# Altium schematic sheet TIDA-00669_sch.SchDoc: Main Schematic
size 431 x 279 mm; Date: Not shown in title block; ApprovedBy: Not shown in title block; CheckedBy: Not shown in title block; Author: Not shown in title block; CompanyName: Not shown in title block; DrawnBy: Gordon Varney; Engineer: Gordon Varney; Organization: Not shown in title block; Address1: Not shown in title block; Address2: Not shown in title block; Address3: Not shown in title block; Address4: Not shown in title block; DocumentNumber: 1; Revision: Use project parameter SCH_Rev; SheetNumber: 2; SheetTotal: 3; PageSetup: Record=PageOptions¦CenterHorizontal=True¦CenterVertical=True¦PrintScale=0.64¦XCorrection=1.00¦YCorrection=1.00¦PrintKind=0¦BorderSize=5000000¦LeftOffset=0¦BottomOffset=0¦Orientation=2¦PaperLength=1000¦PaperWidth=1000¦Scale=100¦PaperSource=15¦PrintQuality=600¦MediaType=1¦DitherType=10¦PrintScaleMode=1¦PaperKind=Letter
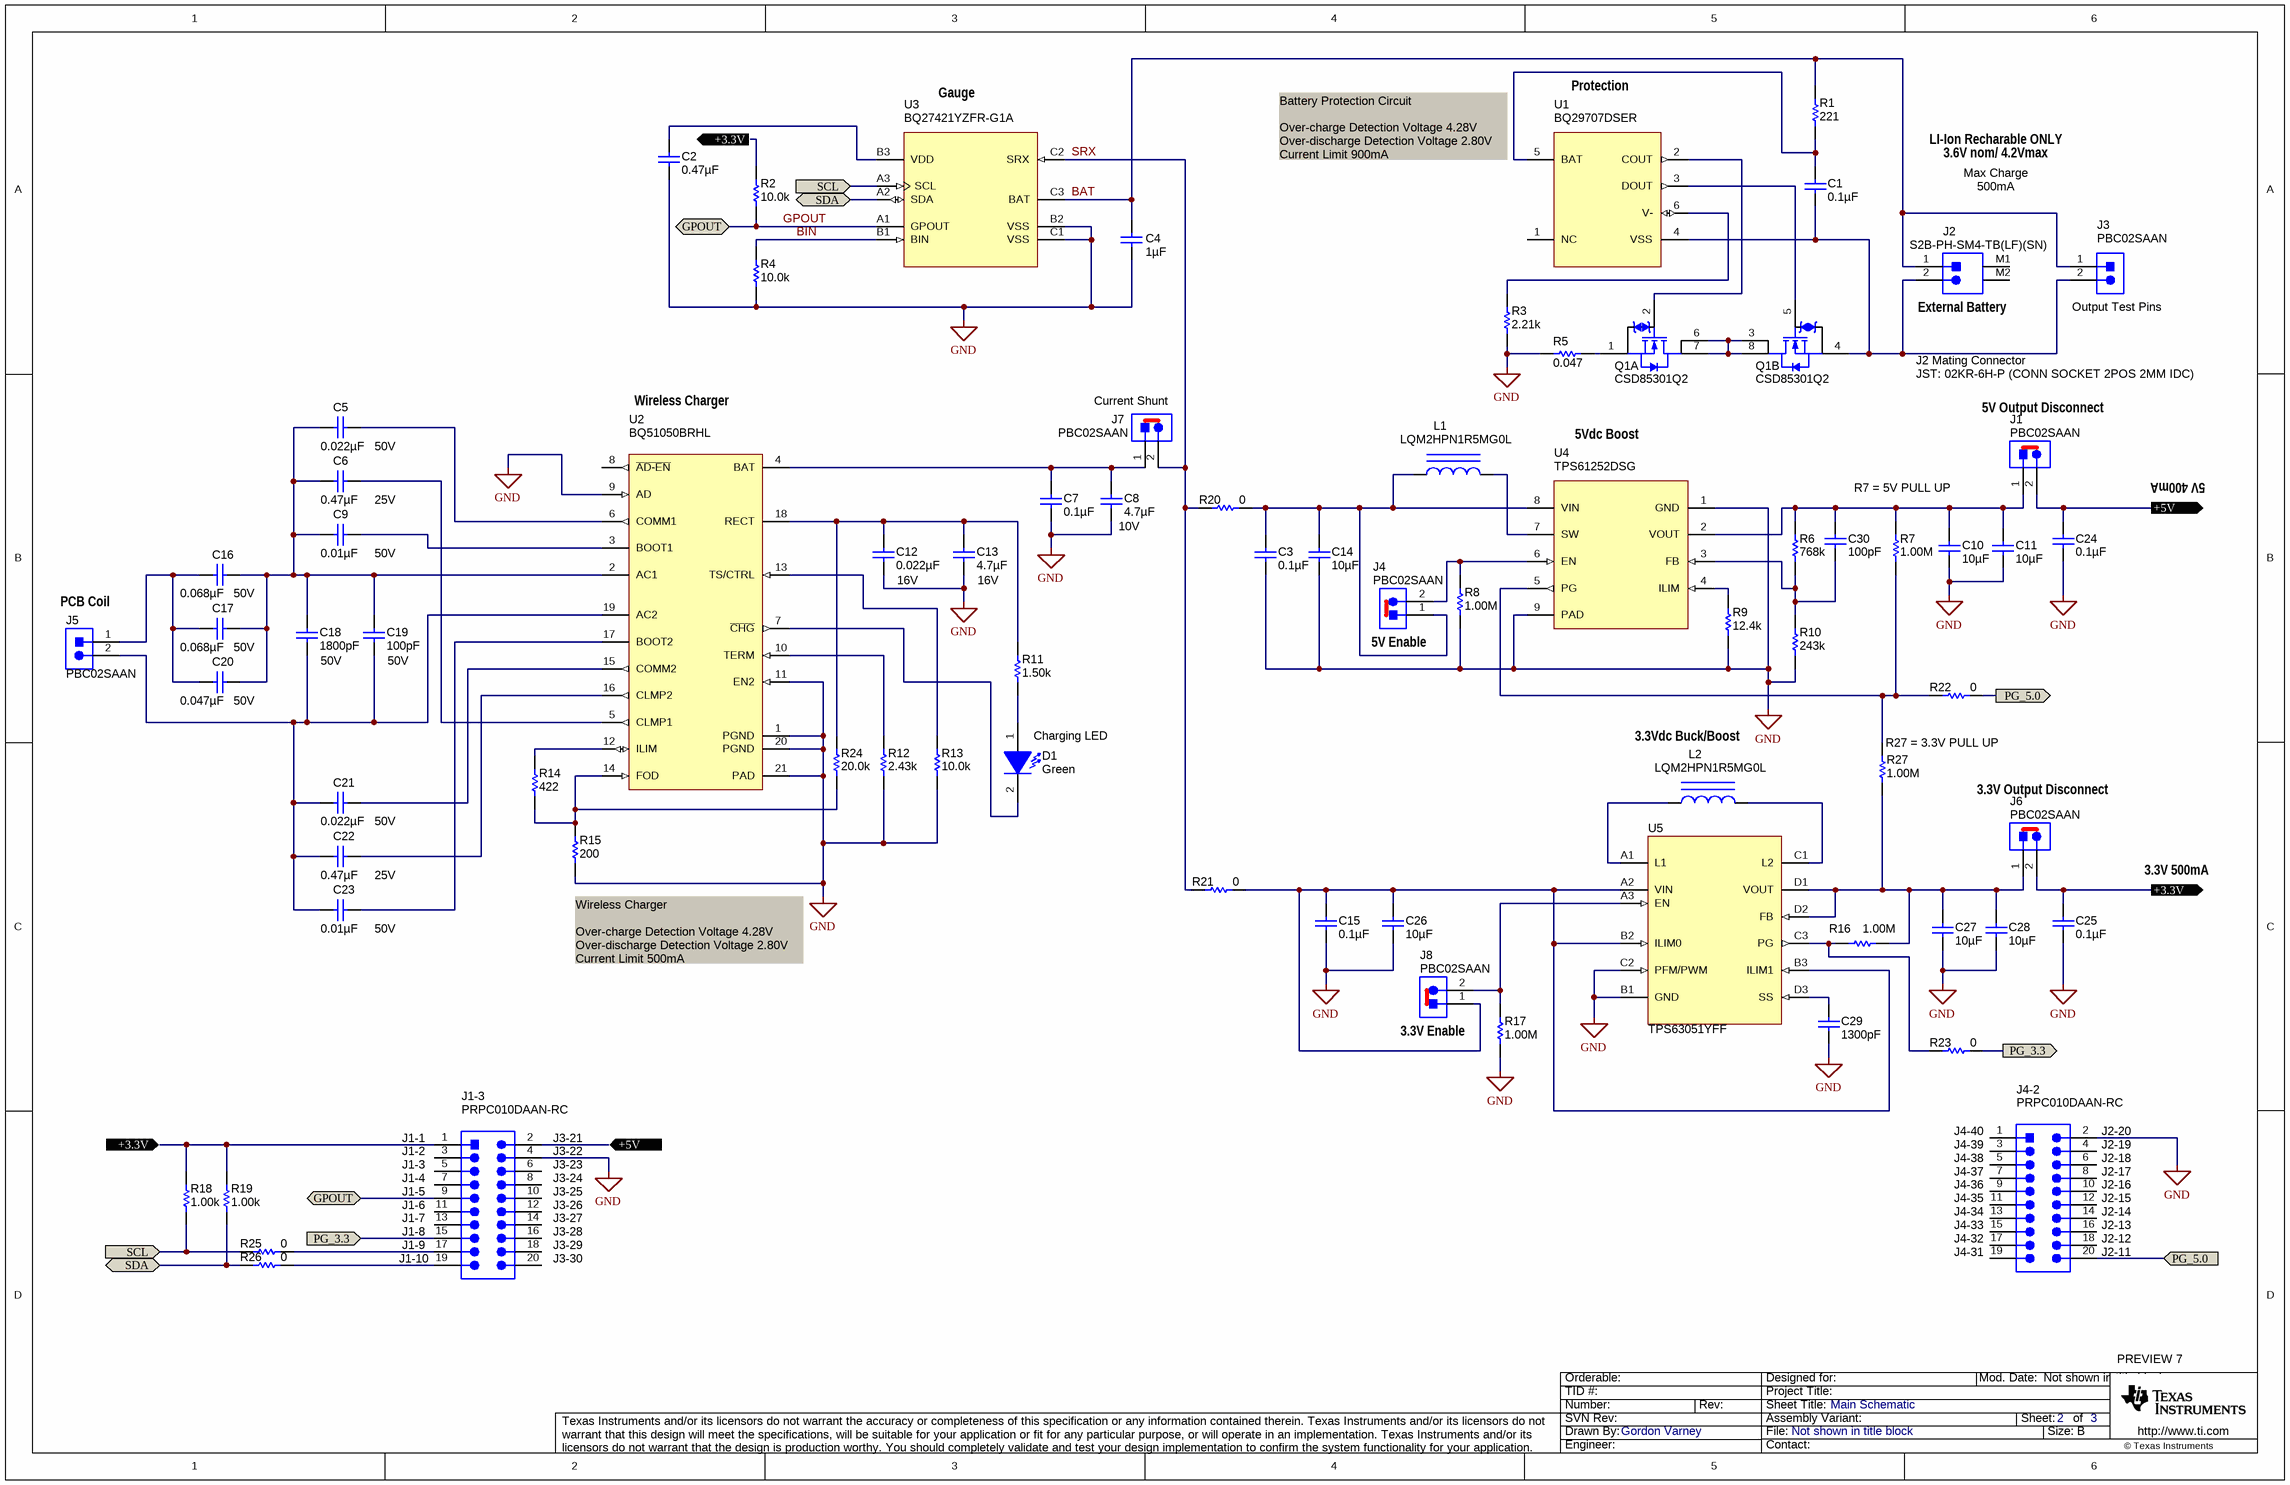
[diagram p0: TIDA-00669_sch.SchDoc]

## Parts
C1  ValueDisplayed: 0.1µF  [0402]  (hidden comment: GRM155R71A104KA01D)
C2  ValueDisplayed: 0.47µF  [0402]  (hidden comment: GRM155R60J474KE19D)
C3  ValueDisplayed: 0.1µF  [0402]  (hidden comment: GRM155R71A104KA01D)
C4  ValueDisplayed: 1µF  [0402]  (hidden comment: GRM155R61A105KE15D)
C5  ValueDisplayed: 0.022µF  Value2: 50V  [0402]  (hidden comment: GRM155R71H223KA12D)
C6  ValueDisplayed: 0.47µF  Value2: 25V  [0603]  (hidden comment: GRM188R71E474KA12D)
C7  ValueDisplayed: 0.1µF  [0402]  (hidden comment: GRM155R71A104KA01D)
C8  ValueDisplayed: 4.7µF  Value2: 10V  [0402]  (hidden comment: C1005X5R1A475K050BC)
C9  ValueDisplayed: 0.01µF  Value2: 50V  [0402]  (hidden comment: C0402C103J5RACTU)
C10  ValueDisplayed: 10µF  [0603]  (hidden comment: C0603C106M9PACTU)
C11  ValueDisplayed: 10µF  [0603]  (hidden comment: C0603C106M9PACTU)
C12  ValueDisplayed: 0.022µF  Value2: 16V  [0402]  (hidden comment: C1005X7R1C223K)
C13  ValueDisplayed: 4.7µF  Value2: 16V  [0603]  (hidden comment: GRM188R61C475KAAJ)
C14  ValueDisplayed: 10µF  [0603]  (hidden comment: C0603C106M9PACTU)
C15  ValueDisplayed: 0.1µF  [0402]  (hidden comment: GRM155R71A104KA01D)
C16  ValueDisplayed: 0.068µF  Value2: 50V  [0402]  (hidden comment: C1005X7R1H683K)
C17  ValueDisplayed: 0.068µF  Value2: 50V  [0402]  (hidden comment: C1005X7R1H683K)
C18  ValueDisplayed: 1800pF  Value2: 50V  [0603]  (hidden comment: GRM1885C1H182JA01D)
C19  ValueDisplayed: 100pF  Value2: 50V  [0402]  (hidden comment: CC0402JRNPO9BN101)
C20  ValueDisplayed: 0.047µF  Value2: 50V  [0603]  (hidden comment: GRM188R71H473KA61D)
C21  ValueDisplayed: 0.022µF  Value2: 50V  [0402]  (hidden comment: GRM155R71H223KA12D)
C22  ValueDisplayed: 0.47µF  Value2: 25V  [0603]  (hidden comment: GRM188R71E474KA12D)
C23  ValueDisplayed: 0.01µF  Value2: 50V  [0402]  (hidden comment: C0402C103J5RACTU)
C24  ValueDisplayed: 0.1µF  [0402]  (hidden comment: GRM155R71A104KA01D)
C25  ValueDisplayed: 0.1µF  [0402]  (hidden comment: GRM155R71A104KA01D)
C26  ValueDisplayed: 10µF  [0603]  (hidden comment: C0603C106M9PACTU)
C27  ValueDisplayed: 10µF  [0603]  (hidden comment: C0603C106M9PACTU)
C28  ValueDisplayed: 10µF  [0603]  (hidden comment: C0603C106M9PACTU)
C29  ValueDisplayed: 1300pF  [0402]  (hidden comment: 0402YC132KAT2A)
C30  ValueDisplayed: 100pF  [0402]  (hidden comment: CC0402JRNPO9BN101)
D1  value Green  [LED_LTST-C190]  (hidden comment: LTST-C190GKT)
J1  PBC02SAAN  [Sullins_PBC02SAAN]
J1-3  PRPC010DAAN-RC  [Sullins_xxxC010DAAN]
J2  S2B-PH-SM4-TB(LF)(SN)  [JST_S2B-PH-SM4-TB]
J3  PBC02SAAN  [Sullins_PBC02SAAN]
J4  PBC02SAAN  [Sullins_PBC02SAAN]
J4-2  PRPC010DAAN-RC  [Sullins_xxxC010DAAN]
J5  PBC02SAAN  [Sullins_PBC02SAAN]
J6  PBC02SAAN  [Sullins_PBC02SAAN]
J7  PBC02SAAN  [Sullins_PBC02SAAN]
J8  PBC02SAAN  [Sullins_PBC02SAAN]
L1  LQM2HPN1R5MG0L  [1008]
L2  LQM2HPN1R5MG0L  [1008]
Q1  CSD85301Q2  [DQK0006B]  (parts A,B of 2)
R1  ValueDisplayed: 221  [0402]  (hidden comment: CRCW0402221RFKED)
R2  ValueDisplayed: 10.0k  [0402]  (hidden comment: CRCW040210K0FKED)
R3  ValueDisplayed: 2.21k  [0402]  (hidden comment: CRCW04022K21FKED)
R4  ValueDisplayed: 10.0k  [0402]  (hidden comment: CRCW040210K0FKED)
R5  ValueDisplayed: 0.047  [0603]  (hidden comment: ERJ-L03KF47MV)
R6  ValueDisplayed: 768k  [0402]  (hidden comment: CRCW0402768KFKED)
R7  ValueDisplayed: 1.00M  [0402]  (hidden comment: CRCW04021M00FKED)
R8  ValueDisplayed: 1.00M  [0402]  (hidden comment: CRCW04021M00FKED)
R9  ValueDisplayed: 12.4k  [0402]  (hidden comment: CRCW040212K4FKED)
R10  ValueDisplayed: 243k  [0402]  (hidden comment: CRCW0402243KFKED)
R11  ValueDisplayed: 1.50k  [0402]  (hidden comment: CRCW04021K50FKED)
R12  ValueDisplayed: 2.43k  [0402]  (hidden comment: CRCW04022K43FKED)
R13  ValueDisplayed: 10.0k  [0402]  (hidden comment: CRCW040210K0FKED)
R14  ValueDisplayed: 422  [0402]  (hidden comment: CRCW0402422RFKED)
R15  ValueDisplayed: 200  [0402]  (hidden comment: CRCW0402200RFKED)
R16  ValueDisplayed: 1.00M  [0402]  (hidden comment: CRCW04021M00FKED)
R17  ValueDisplayed: 1.00M  [0402]  (hidden comment: CRCW04021M00FKED)
R18  ValueDisplayed: 1.00k  [0402]  (hidden comment: CRCW04021K00FKED)
R19  ValueDisplayed: 1.00k  [0402]  (hidden comment: CRCW04021K00FKED)
R20  ValueDisplayed: 0  [0402]  (hidden comment: CRCW04020000Z0ED)
R21  ValueDisplayed: 0  [0402]  (hidden comment: CRCW04020000Z0ED)
R22  ValueDisplayed: 0  [0402]  (hidden comment: CRCW04020000Z0ED)
R23  ValueDisplayed: 0  [0402]  (hidden comment: CRCW04020000Z0ED)
R24  ValueDisplayed: 20.0k  [0402]  (hidden comment: CRCW040220K0FKED)
R25  ValueDisplayed: 0  [0402]  (hidden comment: CRCW04020000Z0ED)
R26  ValueDisplayed: 0  [0402]  (hidden comment: CRCW04020000Z0ED)
R27  ValueDisplayed: 1.00M  [0402]  (hidden comment: CRCW04021M00FKED)
U1  BQ29707DSER  [DSE0006A]
U2  BQ51050BRHL  [RHL0020A]
U3  BQ27421YZFR-G1A  [YZF0009AKAL]
U4  TPS61252DSG  [DSG0008A]
U5  TPS63051YFF  [YFF0012AFAF]

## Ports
+3.3V, +5V, GPOUT, PG_3.3, PG_5.0, SCL, SDA

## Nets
GND: C2.2 C3.2 C4.2 C7.2 C8.2 C10.2 C11.2 C12.2 C13.2 C14.2 C15.2 C24.2 C25.2 C26.2 C27.2 C28.2 C29.2 J1-3.4 J4-2.2 R3.1 R4.1 R5.1 R8.1 R9.2 R10.1 R12.1 R13.1 R15.1 R17.1 U2.1(PGND) U2.9(AD) U2.11(EN2) U2.20(PGND) U2.21(PAD) U3.B2(VSS) U3.C1(VSS) U4.1(GND) U4.9(PAD) U5.B1(GND) U5.C2(PFM/PWM)
+3.3V: C25.1 J1-3.1 J6.2 R2.2 R18.2 R19.2 ; port +3.3V
+5V: C24.1 J1.2 J1-3.2 ; port +5V
BAT: C4.1 J2.1 J3.1 R1.2 U3.C3(BAT)
BIN: R4.2 U3.B1(BIN)
GPOUT: J1-3.9 R2.1 U3.A1(GPOUT) ; port GPOUT
PG_3.3: J1-3.15 R23.2 ; port PG_3.3
PG_5.0: J4-2.20 R22.2 ; port PG_5.0
SCL: R18.1 R25.1 U3.A3(SCL) ; port SCL
SDA: R19.1 R26.1 U3.A2(SDA) ; port SDA
SRX: J7.2 R20.1 R21.1 U3.C2(SRX)
NetC1_1: C1.1 R1.1 U1.5(BAT)
NetC1_2: C1.2 J2.2 J3.2 Q1.4(S2) U1.4(VSS)
NetC2_1: C2.1 U3.B3(VDD)
NetC3_1: C3.1 C14.1 J4.1 L1.1 R20.2 U4.8(VIN)
NetC5_1: C5.1 U2.6(COMM1)
NetC5_2: C5.2 C6.2 C9.2 C16.1 C17.1 C18.1 C19.2 C20.1 U2.2(AC1)
NetC6_1: C6.1 U2.5(CLMP1)
NetC7_1: C7.1 C8.1 J7.1 U2.4(BAT)
NetC9_1: C9.1 U2.3(BOOT1)
NetC10_1: C10.1 C11.1 C30.1 J1.1 R6.2 R7.2 U4.2(VOUT)
NetC12_1: C12.1 C13.1 R11.2 R24.2 U2.18(RECT)
NetC15_1: C15.1 C26.1 J8.1 R21.2 U5.A2(VIN) U5.B2(ILIM0) U5.B3(ILIM1)
NetC16_2: C16.2 C17.2 C20.2 J5.1
NetC18_2: C18.2 C19.1 C21.2 C22.2 C23.2 J5.2 U2.19(AC2)
NetC21_1: C21.1 U2.15(COMM2)
NetC22_1: C22.1 U2.16(CLMP2)
NetC23_1: C23.1 U2.17(BOOT2)
NetC27_1: C27.1 C28.1 J6.1 R16.1 R27.1 U5.D1(VOUT) U5.D2(FB)
NetC29_1: C29.1 U5.D3(SS)
NetC30_2: C30.2 R6.1 R10.2 U4.3(FB)
NetD1_1: D1.1(A) R11.1
NetD1_2: D1.2(K) U2.7(~{CHG})
NetJ1-3_17: J1-3.17 R25.2
NetJ1-3_19: J1-3.19 R26.2
NetJ4_2: J4.2 R8.2 U4.6(EN)
NetJ8_2: J8.2 R17.2 U5.A3(EN)
NetL1_2: L1.2 U4.7(SW)
NetL2_1: L2.1 U5.A1(L1)
NetL2_2: L2.2 U5.C1(L2)
NetQ1_1: Q1.1(S1) R5.2
NetQ1_2: Q1.2(G1) U1.2(COUT)
NetQ1_3: Q1.3(D2) Q1.6(D1) Q1.7(D1) Q1.8(D2)
NetQ1_5: Q1.5(G2) U1.3(DOUT)
NetR3_2: R3.2 U1.6(V-)
NetR7_1: R7.1 R22.1 R27.2 U4.5(PG)
NetR9_1: R9.1 U4.4(ILIM)
NetR12_2: R12.2 U2.10(TERM)
NetR13_2: R13.2 U2.13(TS/CTRL)
NetR14_1: R14.1 R15.2 R24.1 U2.14(FOD)
NetR14_2: R14.2 U2.12(ILIM)
NetR16_2: R16.2 R23.1 U5.C3(PG)

Not connected (* = marked no-connect by the designer): J1-3 3 5 6 7 8 10 11 12 13 14 16 18 20; J2 M1 M2; J4-2 1 3 4 5 6 7 8 9 10 11 12 13 14 15 16 17 18 19; U1 1(NC); U2 8(~{AD-EN})

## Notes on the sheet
- Gauge
- Protection
- (near U1) Battery Protection Circuit
  Over-charge Detection Voltage 4.28V
  Over-discharge Detection Voltage 2.80V
  Current Limit 900mA
- LI-Ion Recharable ONLY
- 3.6V nom/ 4.2Vmax
- Max Charge
- 500mA
- (near J2) External Battery
- (near J3) Output Test Pins
- J2 Mating Connector
- Wireless Charger
- (near J7) Current Shunt
- 5Vdc Boost
- JST: 02KR-6H-P (CONN SOCKET 2POS 2MM IDC)
- (near J1) 5V Output Disconnect
- R7 = 5V PULL UP
- 5V 400mA
- (near J5) PCB Coil
- (near J4) 5V Enable
- (near D1) Charging LED
- 3.3Vdc Buck/Boost
- (near R27) R27 = 3.3V PULL UP
- 3.3V Output Disconnect
- 3.3V 500mA
- (near R15) Wireless Charger
  Over-charge Detection Voltage 4.28V
  Over-discharge Detection Voltage 2.80V
  Current Limit 500mA
- 3.3V Enable
- (near J1-3) J1-1
- (near J1-3) J1-2
- (near J1-3) J1-3
- (near J1-3) J3-21
- (near J1-3) J3-22
- (near J1-3) J3-23
- (near J4-2) J4-37
- (near J4-2) J4-38
- (near J4-2) J4-39
- (near J4-2) J4-40
- (near J4-2) J2-17
- (near J4-2) J2-18
- (near J4-2) J2-19
- (near J4-2) J2-20
- (near J1-3) J1-4
- (near J1-3) J1-5
- (near J1-3) J1-6
- (near J1-3) J1-7
- (near J1-3) J1-8
- (near J1-3) J1-9
- (near J1-3) J3-24
- (near J1-3) J3-25
- (near J1-3) J3-26
- (near J1-3) J3-27
- (near J1-3) J3-28
- (near J1-3) J3-29
- (near J4-2) J4-32
- (near J4-2) J4-33
- (near J4-2) J4-34
- (near J4-2) J4-35
- (near J4-2) J4-36
- (near J4-2) J2-12
- (near J4-2) J2-13
- (near J4-2) J2-14
- (near J4-2) J2-15
- (near J4-2) J2-16
- (near J1-3) J1-10
- (near J1-3) J3-30
- (near J4-2) J4-31
- (near J4-2) J2-11
- PREVIEW 7

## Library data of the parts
C1 C3 C7 C15 C24 C25 = GRM155R71A104KA01D: CAP, CERM, 0.1 µF, 10 V, +/- 10%, X7R, 0402; Manufacturer: MuRata; Polarized: N; CompType: Capacitor; Value: 0.1uF; U/M: EA; Cap_F: 0.0000001; Tolerance_%: 10; Value1: Unknown; Value2: 10V; TaMin_C: -55; TaMax_C: 125
C2 = GRM155R60J474KE19D: CAP, CERM, 0.47 µF, 6.3 V, +/- 10%, X5R, 0402; Manufacturer: MuRata; Polarized: N; CompType: Capacitor; Value: 0.47uF; U/M: EA; Cap_F: 0.00000047; Tolerance_%: 10; Value1: Unknown; VDC_V: 6.3; Value2: 6.3V; TaMin_C: -55; TaMax_C: 85
C4 = GRM155R61A105KE15D: CAP, CERM, 1 µF, 10 V, +/- 10%, X5R, 0402; Manufacturer: MuRata; Polarized: N; CompType: Capacitor; Value: 1uF; U/M: EA; Cap_F: 0.000001; Tolerance_%: 10; Value1: Unknown; Value2: 10V; TaMin_C: -55; TaMax_C: 85
C5 C21 = GRM155R71H223KA12D: CAP, CERM, 0.022 µF, 50 V, +/- 10%, X7R, 0402; Manufacturer: MuRata; Polarized: N; CompType: Capacitor; Value: 0.022uF; U/M: EA; Cap_F: 0.000000022; Tolerance_%: 10; Value1: Unknown; VDC_V: 50; TaMin_C: -55; TaMax_C: 125
C6 C22 = GRM188R71E474KA12D: CAP, CERM, 0.47 µF, 25 V, +/- 10%, X7R, 0603; Manufacturer: MuRata; Polarized: N; CompType: Capacitor; Value: 0.47uF; U/M: EA; Cap_F: 0.00000047; Tolerance_%: 10; Value1: Unknown; VDC_V: 25; TaMin_C: -55; TaMax_C: 125
C8 = C1005X5R1A475K050BC: CAP, CERM, 4.7 µF, 10 V, +/- 10%, X5R, 0402; Manufacturer: TDK; Polarized: N; CompType: Capacitor; Value: 4.7uF; U/M: EA; Cap_F: 0.0000047; Tolerance_%: 10; Value1: Unknown; TaMin_C: -55; TaMax_C: 85
C9 C23 = C0402C103J5RACTU: CAP, CERM, 0.01 µF, 50 V, +/- 5%, X7R, 0402; Manufacturer: Kemet; Polarized: N; CompType: Capacitor; Value: 0.01uF; U/M: EA; Cap_F: 0.00000001; Tolerance_%: 5; Value1: Unknown; VDC_V: 50; TaMin_C: -55; TaMax_C: 125
C10 C11 C14 C26-C28 = C0603C106M9PACTU: CAP, CERM, 10 µF, 6.3 V, +/- 20%, X5R, 0603; Manufacturer: Kemet; Polarized: N; CompType: Capacitor; Value: 10uF; U/M: EA; Cap_F: 0.00001; Tolerance_%: 20; ESR_ohm: 0.004; Value1: 0.004 ohm; VDC_V: 6.3; Value2: 6.3V; IRMS_A: 8.9; TaMin_C: -55; TaMax_C: 85
C12 = C1005X7R1C223K: CAP, CERM, 0.022 µF, 16 V, +/- 10%, X7R, 0402; Manufacturer: TDK; Polarized: N; CompType: Capacitor; Value: 0.022uF; U/M: EA; Cap_F: 0.000000022; Tolerance_%: 10; ESR_ohm: 0.0419; Value1: 0.0419 ohm; VDC_V: 16; TaMin_C: -55; TaMax_C: 125
C13 = GRM188R61C475KAAJ: CAP, CERM, 4.7 µF, 16 V, +/- 10%, X5R, 0603; Manufacturer: MuRata; Polarized: N; CompType: Capacitor; Value: 4.7uF; U/M: EA; Cap_F: 0.0000047; Tolerance_%: 10; Value1: Unknown; VDC_V: 16; TaMin_C: -55; TaMax_C: 85
C16 C17 = C1005X7R1H683K: CAP, CERM, 0.068 µF, 50 V, +/- 10%, X7R, 0402; Manufacturer: TDK; Polarized: N; CompType: Capacitor; Value: 0.068uF; U/M: EA; Cap_F: 0.000000068; Tolerance_%: 10; Value1: Unknown; VDC_V: 50; TaMin_C: -55; TaMax_C: 125
C18 = GRM1885C1H182JA01D: CAP, CERM, 1800 pF, 50 V, +/- 5%, C0G/NP0, 0603; Manufacturer: MuRata; Polarized: N; CompType: Capacitor; Value: 1800pF; U/M: EA; Cap_F: 0.0000000018; Tolerance_%: 5; Value1: Unknown; VDC_V: 50; TaMin_C: -55; TaMax_C: 125
C19 = CC0402JRNPO9BN101: CAP, CERM, 100 pF, 50 V, +/- 5%, C0G/NP0, 0402; Manufacturer: Yageo America; Polarized: N; CompType: Capacitor; Value: 100pF; U/M: EA; Cap_F: 0.0000000001; Tolerance_%: 5; Value1: Unknown; VDC_V: 50; TaMin_C: -55; TaMax_C: 125
C20 = GRM188R71H473KA61D: CAP, CERM, 0.047 µF, 50 V, +/- 10%, X7R, 0603; Manufacturer: MuRata; Polarized: N; CompType: Capacitor; Value: 0.047uF; U/M: EA; Cap_F: 0.000000047; Tolerance_%: 10; Value1: Unknown; VDC_V: 50; TaMin_C: -55; TaMax_C: 125
C29 = 0402YC132KAT2A: CAP, CERM, 1300 pF, 16 V, +/- 10%, X7R, 0402; Manufacturer: AVX; Polarized: N; CompType: Capacitor; Value: 1300pF; U/M: EA; Cap_F: 0.0000000013; Tolerance_%: 10; Value1: Unknown; VDC_V: 16; Value2: 16V; TaMin_C: -55; TaMax_C: 125
C30 = CC0402JRNPO9BN101: CAP, CERM, 100 pF, 50 V, +/- 5%, C0G/NP0, 0402; Manufacturer: Yageo America; Polarized: N; CompType: Capacitor; Value: 100pF; U/M: EA; Cap_F: 0.0000000001; Tolerance_%: 5; Value1: Unknown; VDC_V: 50; Value2: 50V; TaMin_C: -55; TaMax_C: 125
D1 = LTST-C190GKT: LED, Green, SMD; Manufacturer: Lite-On; Vf_V: 2.1; Value2: 2.1V; Io_A: 0.02; Power_TotalModule: 0.1; Value1: 0.1W; U/M: EA
J1 J3-J8 = PBC02SAAN: Header, 100mil, 2x1, Gold, TH; Manufacturer: Sullins Connector Solutions; SymbolCreator: a0412235; U/M: EA
J1-3 J4-2 = PRPC010DAAN-RC: Header, 2.54mm, 10x2, Gold, TH; Manufacturer: Sullins Connector Solutions; SymbolCreator: a0412235; U/M: EA
J2 = S2B-PH-SM4-TB(LF)(SN): Header (shrouded), 2mm, 2x1, R/A, SMT; Manufacturer: JST Manufacturing; SymbolCreator: x0208326; U/M: EA; Note: mating conn: 02KR-6H-P (CONN SOCKET 2POS 2MM IDC)
L1 L2 = LQM2HPN1R5MG0L: Inductor, Multilayer, Ferrite, 1.5 µH, 1.5 A, 0.07 ohm, SMD; Manufacturer: MuRata; Value: 1.5uH; Ind_H: 1.5E-6; ValueDisplayed: 1.5µH; Imax_A: 1.5; Irms: 1.5A @ 40C rise; DCR_ohm: 0.07; Value2: 1.5A
Q1 = CSD85301Q2: MOSFET, N-CH, 20 V, 6.7 A,; Manufacturer: Texas Instruments; Alternate Manufacturer: None; SymbolCreator: a0411947; U/M: EA; ChType: N; Value: 20V; VdsMax_V: 20; Value1: 0.023 ohm; Rdson45_ohm: 0.023; Value2: 4.2 nC; QgTyp_nC: 4.2; Vgs_V: 10; IdsMax_A: 6.7
R1 = CRCW0402221RFKED: RES, 221, 1%, 0.063 W, 0402; Manufacturer: Vishay-Dale; CompType: Resistor; Value: 221; Value_Code: 221R; Tolerance_%: 1; Power_W: 0.063; Value2: 0.063W; VDC_V: 50; TempCo: 100 ppm/C; EIA_Code: E96; U/M: EA
R2 R4 R13 = CRCW040210K0FKED: RES, 10.0 k, 1%, 0.063 W, 0402; Manufacturer: Vishay-Dale; CompType: Resistor; Value: 10.0k; Res_ohm: 10000; Value_Code: 10k0; Tolerance_%: 1; Power_W: 0.063; Value2: 0.063W; VDC_V: 50; TempCo: 100 ppm/C; EIA_Code: E96; U/M: EA
R3 = CRCW04022K21FKED: RES, 2.21 k, 1%, 0.063 W, 0402; Manufacturer: Vishay-Dale; CompType: Resistor; Value: 2.21k; Res_ohm: 2210; Value_Code: 2k21; Tolerance_%: 1; Power_W: 0.063; Value2: 0.063W; VDC_V: 50; TempCo: 100 ppm/C; EIA_Code: E96; U/M: EA
R5 = ERJ-L03KF47MV: RES, 0.047, 1%, 0.1 W, 0603; Manufacturer: Panasonic; CompType: Resistor; Value: 0.047; Value_Code: R047; Tolerance_%: 1; Power_W: 0.1; Value2: 0.1W; TempCo: 200 ppm/C; EIA_Code: E96; U/M: EA
R6 = CRCW0402768KFKED: RES, 768 k, 1%, 0.063 W, 0402; Manufacturer: Vishay-Dale; CompType: Resistor; Value: 768k; Res_ohm: 768000; Tolerance_%: 1; Power_W: 0.063; Value2: 0.063W; VDC_V: 50; TempCo: 100 ppm/C; EIA_Code: E96; U/M: EA
R7 R8 R16 R17 R27 = CRCW04021M00FKED: RES, 1.00 M, 1%, 0.063 W, 0402; Manufacturer: Vishay-Dale; CompType: Resistor; Value: 1.00Meg; Res_ohm: 1000000; Value_Code: 1M00; Tolerance_%: 1; Power_W: 0.063; Value2: 0.063W; VDC_V: 50; TempCo: 100 ppm/C; EIA_Code: E96; U/M: EA
R9 = CRCW040212K4FKED: RES, 12.4 k, 1%, 0.063 W, 0402; Manufacturer: Vishay-Dale; CompType: Resistor; Value: 12.4k; Res_ohm: 12400; Value_Code: 12k4; Tolerance_%: 1; Power_W: 0.063; Value2: 0.063W; VDC_V: 50; TempCo: 100 ppm/C; EIA_Code: E96; U/M: EA
R10 = CRCW0402243KFKED: RES, 243 k, 1%, 0.063 W, 0402; Manufacturer: Vishay-Dale; CompType: Resistor; Value: 243k; Res_ohm: 243000; Tolerance_%: 1; Power_W: 0.063; Value2: 0.063W; VDC_V: 50; TempCo: 100 ppm/C; EIA_Code: E96; U/M: EA
R11 = CRCW04021K50FKED: RES, 1.50 k, 1%, 0.063 W, 0402; Manufacturer: Vishay-Dale; CompType: Resistor; Value: 1.50k; Res_ohm: 1500; Value_Code: 1k50; Tolerance_%: 1; Power_W: 0.063; Value2: 0.063W; VDC_V: 50; TempCo: 100 ppm/C; EIA_Code: E96; U/M: EA
R12 = CRCW04022K43FKED: RES, 2.43 k, 1%, 0.063 W, 0402; Manufacturer: Vishay-Dale; CompType: Resistor; Value: 2.43k; Res_ohm: 2430; Value_Code: 2k43; Tolerance_%: 1; Power_W: 0.063; Value2: 0.063W; VDC_V: 50; TempCo: 100 ppm/C; EIA_Code: E96; U/M: EA
R14 = CRCW0402422RFKED: RES, 422, 1%, 0.063 W, 0402; Manufacturer: Vishay-Dale; CompType: Resistor; Value: 422; Value_Code: 422R; Tolerance_%: 1; Power_W: 0.063; Value2: 0.063W; VDC_V: 50; TempCo: 100 ppm/C; EIA_Code: E96; U/M: EA; AEC Category: Q200
R15 = CRCW0402200RFKED: RES, 200, 1%, 0.063 W, 0402; Manufacturer: Vishay-Dale; CompType: Resistor; Value: 200; Value_Code: 200R; Tolerance_%: 1; Power_W: 0.063; Value2: 0.063W; VDC_V: 50; TempCo: 100 ppm/C; EIA_Code: E96; U/M: EA; AEC Category: Q200
R18 R19 = CRCW04021K00FKED: RES, 1.00 k, 1%, 0.063 W, 0402; Manufacturer: Vishay-Dale; CompType: Resistor; Value: 1.00k; Res_ohm: 1000; Value_Code: 1k00; Tolerance_%: 1; Power_W: 0.063; Value2: 0.063W; VDC_V: 50; TempCo: 100 ppm/C; EIA_Code: E96; U/M: EA
R20-R23 R25 R26 = CRCW04020000Z0ED: RES, 0, 5%, 0.063 W, 0402; Manufacturer: Vishay-Dale; CompType: Resistor; Value: 0; Value_Code: 0000; Tolerance_%: 5; Power_W: 0.063; Value2: 0.063W; VDC_V: 50; TempCo: 200 ppm/C; EIA_Code: E24; U/M: EA
R24 = CRCW040220K0FKED: RES, 20.0 k, 1%, 0.063 W, 0402; Manufacturer: Vishay-Dale; CompType: Resistor; Value: 20.0k; Res_ohm: 20000; Value_Code: 20k0; Tolerance_%: 1; Power_W: 0.063; Value2: 0.063W; VDC_V: 50; TempCo: 100 ppm/C; EIA_Code: E96; U/M: EA
U1 = BQ29700DSER: Cost-Effective Voltage and Current Protection Integrated Circuit for Single-Cell Li-Ion/Li-Polymer Batteries, DSE0006A; Alternate PartNumber: BQ29707DSET; Manufacturer: Texas Instruments; SymbolCreator: a0412235; CompType: IC; U/M: EA
U2 = BQ51050BRHL: High-Efficiency Qi v1.1-Compliant Wireless Power Receiver and Battery Charger, RHL0020A; Manufacturer: Texas Instruments; SymbolCreator: a0411947; CompType: IC; U/M: EA
U3 = BQ27421YZFR-G1A: System-Side Impedance Track Fuel Gauge With Integrated Sense Resistor, YZF0009AKAL; Alternate PartNumber: BQ27421YZFT-G1A; Manufacturer: Texas Instruments; SymbolCreator: Altium; CompType: IC; U/M: EA
U4 = TPS61252DSG: TINY 1.5-A BOOST CONVERTER WITH ADJUSTABLE INPUT CURRENT LIMIT, DSG0008A; Manufacturer: Texas Instruments; SymbolCreator: a0799628; CompType: IC; U/M: EA
U5 = TPS63051YFF: SINGLE INDUCTOR BUCK-BOOST WITH 1A SWITCHES AND ADJUSTABLE SOFT START, YFF0012AFAF; Manufacturer: Texas Instruments; SymbolCreator: a0799628; CompType: IC; U/M: EA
